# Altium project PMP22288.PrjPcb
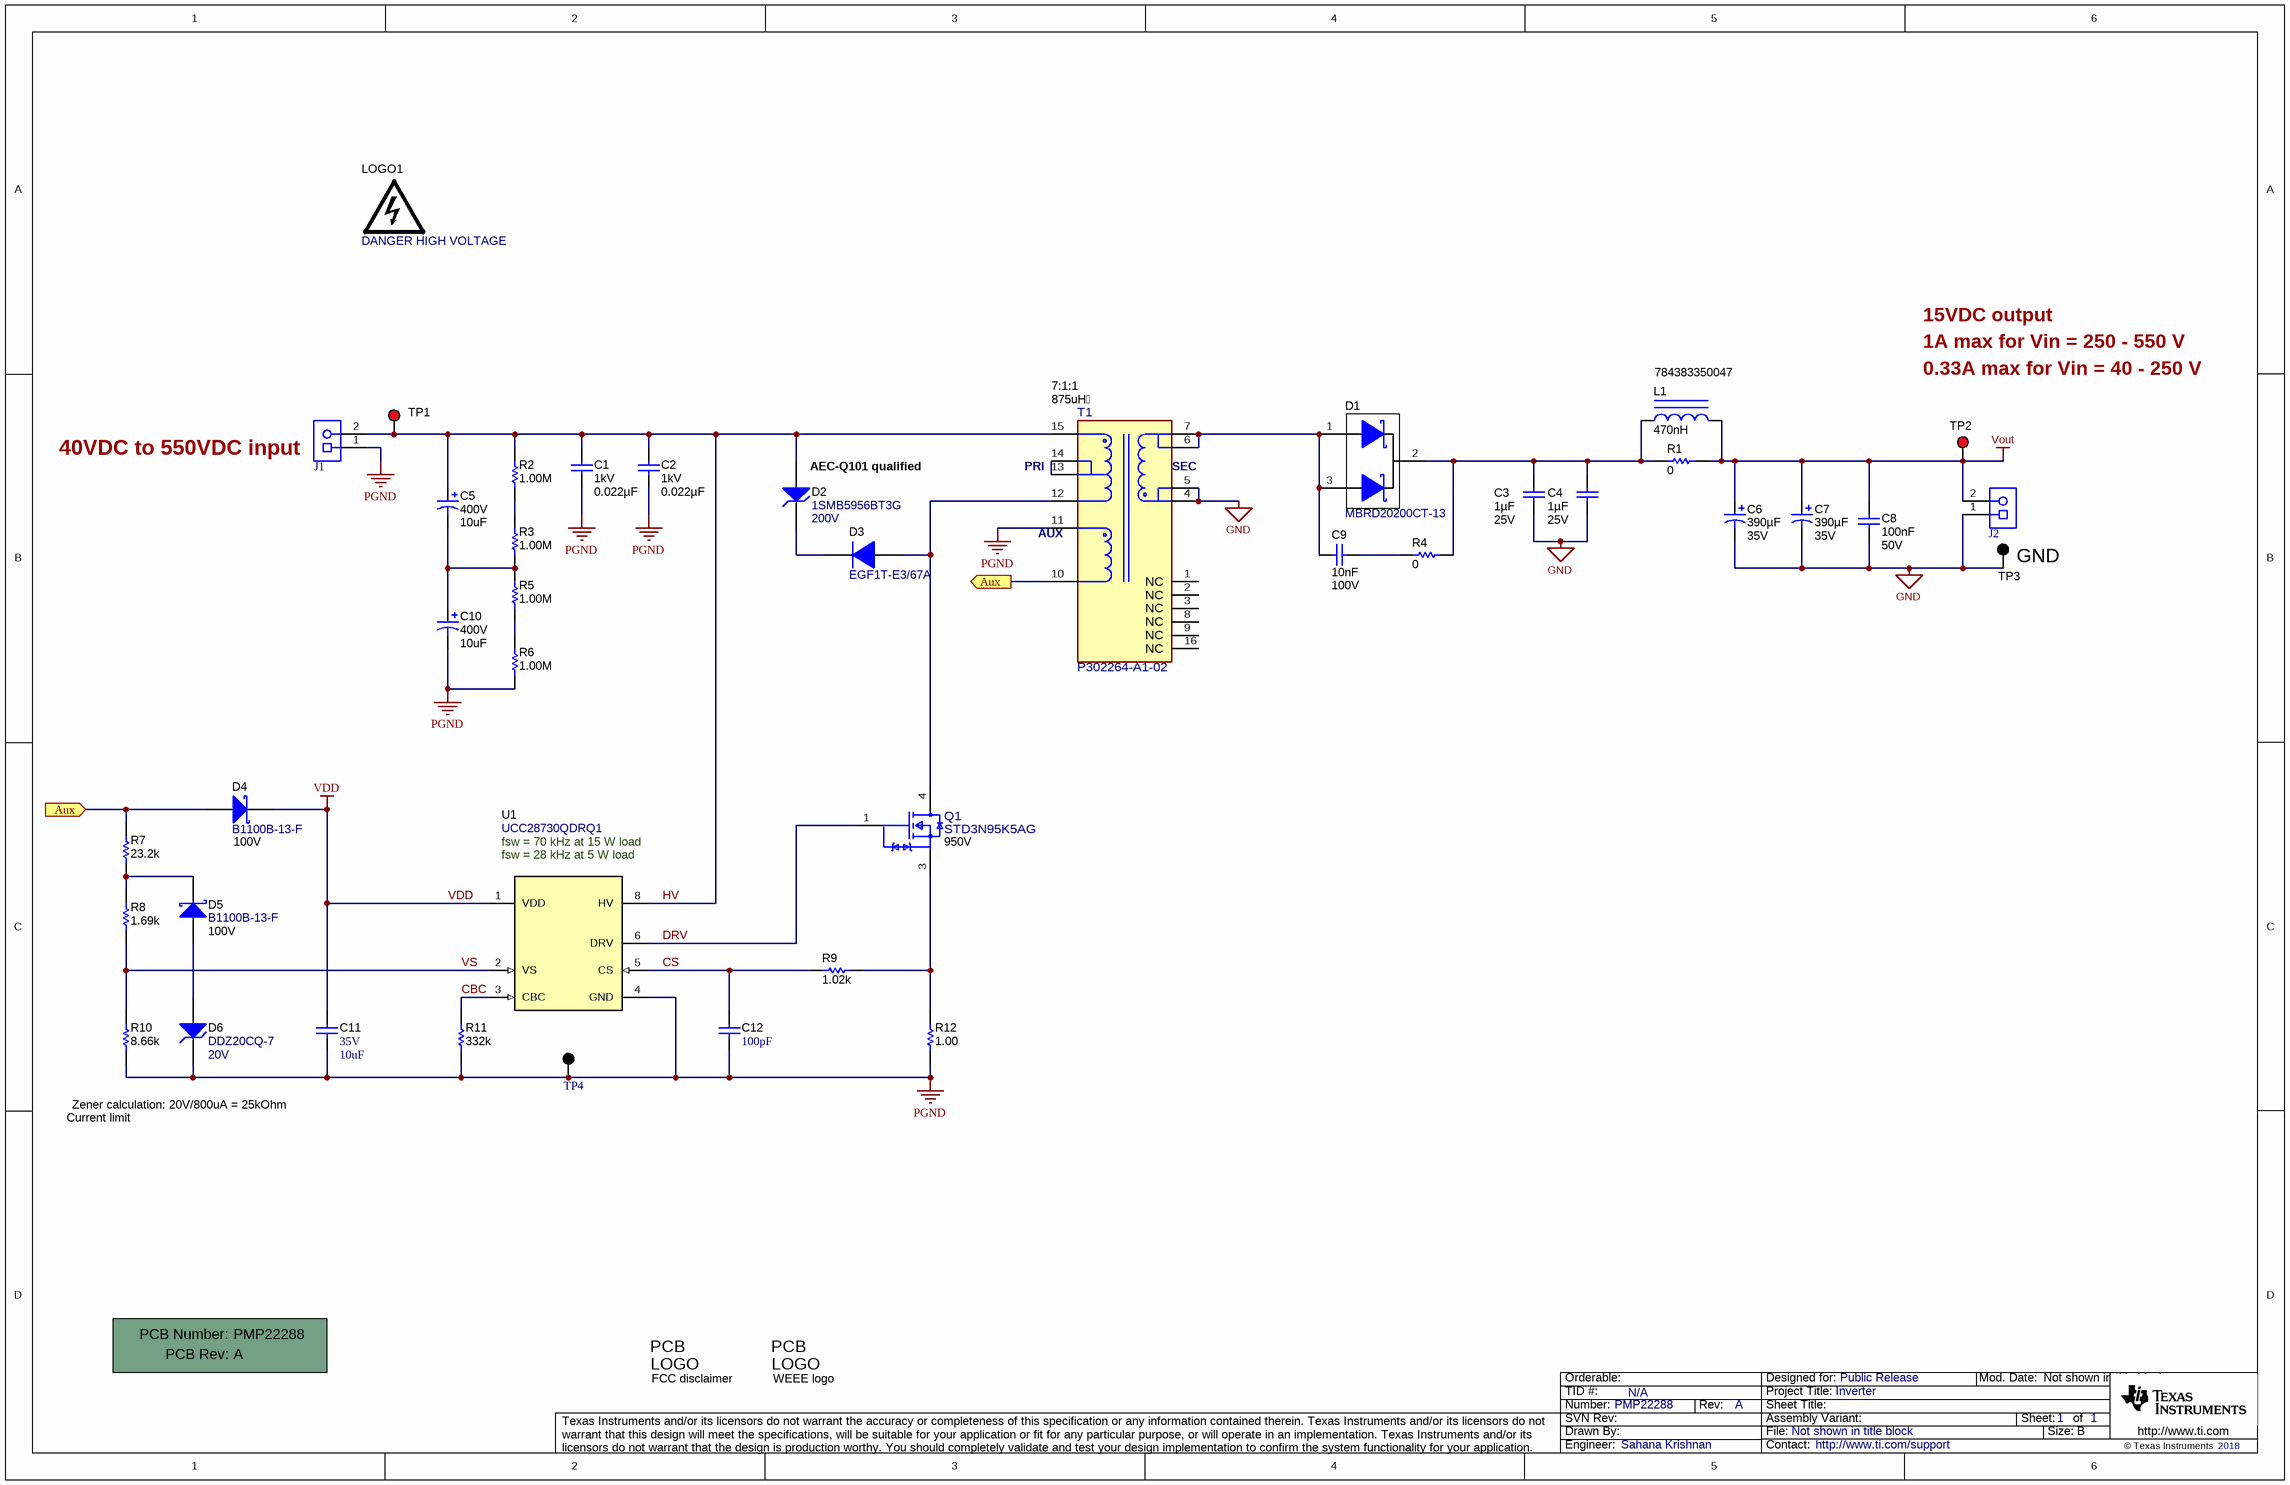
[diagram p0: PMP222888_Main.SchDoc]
CopyrightYear: 2018; PCB_Layout: Sahana Krishnan; PCB_Rev: A; PRJ_Customer: Public Release; PRJ_Engineer: Sahana Krishnan; PRJ_Number: PMP22288; PRJ_Title: Inverter; SCH_Rev: A; TechSupport: http://www.ti.com/support; TID: N/A
1 sheet, 44 parts. Net scope: flat (ports and power ports of the same name join across sheets).
Board file: PMP22288_PCB.PcbDoc

## Sheet PMP222888_Main.SchDoc
size 431 x 279 mm; Date: Not shown in title block; ApprovedBy: Not shown in title block; CheckedBy: Not shown in title block; Author: Not shown in title block; CompanyName: Not shown in title block; Engineer: Not shown in title block; Organization: Not shown in title block; Address1: Not shown in title block; Address2: Not shown in title block; Address3: Not shown in title block; Address4: Not shown in title block; DocumentNumber: 1; Revision: Use project parameter SCH_Rev; SheetNumber: 1; SheetTotal: 1; PageSetup: Record=PageOptions¦CenterHorizontal=True¦CenterVertical=True¦PrintScale=1.00¦XCorrection=1.00¦YCorrection=1.00¦PrintKind=0¦BorderSize=5000000¦LeftOffset=0¦BottomOffset=0¦Orientation=2¦PaperLength=1000¦PaperWidth=1000¦Scale=100¦PaperSource=15¦PrintQuality=600¦MediaType=1¦DitherType=10¦PaperKind=Letter¦PrintScaleMode=1

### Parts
!PCB1  Printed Circuit Board  (value not drawn)  (mechanical)
C1  VDC_V: 1kV  ValueDisplayed: 0.022µF  [1206_190]  (hidden comment: C1206C223KDRACTU)
C2  VDC_V: 1kV  ValueDisplayed: 0.022µF  [1206_190]  (hidden comment: C1206C223KDRACTU)
C3  Cap_F: 1µF  VDC_V: 25V  [0603]  (hidden comment: GRM188R71E105KA12D)
C4  Cap_F: 1µF  VDC_V: 25V  [0603]  (hidden comment: GRM188R71E105KA12D)
C5  VDC_V: 400V  ValueDisplayed: 10uF  [ULV_1000x1350]  (hidden comment: ULV2G100MNL1GS)
C6  ValueDisplayed: 390µF  VDC_V: 35V  [FC_1250x1500]  (hidden comment: EEU-FC1V391S)
C7  ValueDisplayed: 390µF  VDC_V: 35V  [FC_1250x1500]  (hidden comment: EEU-FC1V391S)
C8  Cap_F: 100nF  VDC_V: 50V  [0603]  (hidden comment: C0603C104K5RACAUTO)
C9  Cap_F: 10nF  VDC_V: 100V  [0603]  (hidden comment: CGA3E2X7R2A103K080AA)
C10  VDC_V: 400V  ValueDisplayed: 10uF  [ULV_1000x1350]  (hidden comment: ULV2G100MNL1GS)
C11  VDC_V: 35V  ValueDisplayed: 10uF  [1206_190]  (hidden comment: CGA5L1X7R1V106K160AC)
C12  ValueDisplayed: 100pF  [0603]  (hidden comment: CGA3E2NP01H101J080AA)
D1  MBRD20200CT-13  [DPAK]
D2  1SMB5956BT3G  value 200V  [SMB]
D3  EGF1T-E3/67A  [DO-214BA]
D4  B1100B-13-F  value 100V  [SMB]
D5  B1100B-13-F  value 100V  [SMB]
D6  DDZ20CQ-7  value 20V  [SOD-123]
J1  ED120/2DS  [On-Shore_ED120_2DS]  (value not drawn)
J2  ED120/2DS  [On-Shore_ED120_2DS]  (value not drawn)
L1  784383350047  ValueDisplayed: 470nH  [WE-MAIA_3015]
LOGO1  DANGER HIGH VOLTAGE  [IEC_HighVoltage_Small]  (no BOM)
Logo2  FCC disclaimer  [FCC_disclaimer]  (no BOM)
Logo3  WEEE logo  [WEEE_Minimum]  (no BOM)
Q1  STD3N95K5AG  VdsMax_V: 950V  [FP-STD3N95K5AG_DPAK-MFG]
R1  ValueDisplayed: 0  [1206]  (hidden comment: CRCW12060000Z0EA)
R2  ValueDisplayed: 1.00M  [1206]  (hidden comment: CRCW12061M00FKEA)
R3  ValueDisplayed: 1.00M  [1206]  (hidden comment: CRCW12061M00FKEA)
R4  ValueDisplayed: 0  [1206]  (hidden comment: CRCW12060000Z0EA)
R5  ValueDisplayed: 1.00M  [1206]  (hidden comment: CRCW12061M00FKEA)
R6  ValueDisplayed: 1.00M  [1206]  (hidden comment: CRCW12061M00FKEA)
R7  ValueDisplayed: 23.2k  [0603]  (hidden comment: CRCW060323K2FKEA)
R8  ValueDisplayed: 1.69k  [0603]  (hidden comment: CRCW06031K69FKEA)
R9  ValueDisplayed: 1.02k  [0603]  (hidden comment: CRCW06031K02FKEA)
R10  ValueDisplayed: 8.66k  [0603]  (hidden comment: CRCW06038K66FKEA)
R11  ValueDisplayed: 332k  [0402L]  (hidden comment: CRCW0402332KFKED)
R12  ValueDisplayed: 1.00  [1206]  (hidden comment: CSR1206FT1R00)
T1  P302264-A1-02  Ns1toNp: 7:1:1  Ind_H: 875uH  [FP-P302264-A1-51_SMD_TRANSFORMER_26MM0_22MM8-MFG]
TP1  5000  [Keystone5000]  (value not drawn)
TP2  5000  [Keystone5000]  (value not drawn)
TP3  5001  [Keystone5001]  (value not drawn)
TP4  5011  [Keystone5011]  (value not drawn)
U1  UCC28730QDRQ1  [D0007A_N]

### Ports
Aux (in), Aux (out)

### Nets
GND: C3.2 C4.2 C6.2(-) C7.2(-) C8.2 J2.1 T1.4 T1.5 TP3.1
PGND: C1.2 C2.2 C10.2(-) C11.2 C12.2 D6.1(K) J1.1 R6.2 R10.1 R11.1 R12.1 T1.11 TP4.1 U1.4(GND)
VDD: C11.1 D4.1(K) U1.1(VDD)
Vout: C6.1(+) C7.1(+) C8.1 J2.2 L1.2 R1.2 TP2.1
Aux: D4.2(A) R7.2 T1.10 ; port Aux
CBC: R11.2 U1.3(CBC)
CS: C12.1 R9.1 U1.5(CS)
DRV: Q1.1(G) U1.6(DRV)
HV: C1.1 C2.1 C5.1(+) D2.2(A) J1.2 R2.1 T1.15 TP1.1 U1.8(HV)
VS: R8.1 R10.2 U1.2(VS)
NetC3_1: C3.1 C4.1 D1.2(K) L1.1 R1.1 R4.2
NetC5_2: C5.2(-) C10.1(+) R3.2 R5.1
NetC9_1: C9.1 R4.1
NetC9_2: C9.2 D1.1(A) D1.3(A) T1.6 T1.7
NetD2_1: D2.1(K) D3.1(K)
NetD3_2: D3.2(A) Q1.4(D) T1.12
NetD5_1: D5.1(K) R7.1 R8.2
NetD5_2: D5.2(A) D6.2(A)
NetQ1_3: Q1.3(S) R9.2 R12.2
NetR2_2: R2.2 R3.1
NetR5_2: R5.2 R6.1
NetT1_13: T1.13 T1.14

Not connected (* = marked no-connect by the designer): T1 1(NC) 2(NC) 3(NC) 8(NC) 9(NC) 16(NC)

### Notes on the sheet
- 1A max for Vin = 250 - 550 V
- 15VDC output
- 0.33A max for Vin = 40 - 250 V
- (near J1) 40VDC to 550VDC input
- (near D2) AEC-Q101 qualified
- (near T1) PRI
- (near T1) SEC
- (near T1) AUX
- (near TP3) GND
- (near U1) fsw = 28 kHz at 5 W load
- fsw = 70 kHz at 15 W load
- Zener calculation: 20V/800uA = 25kOhm
- Current limit

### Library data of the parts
!PCB1 = CMP-0003618-2: Manufacturer: Any; PartNumber: PMP22288
C1 C2 = CMP-0084048-1: CAP, CERM, 0.022 µF, 1000 V,+/- 10%, X7R, AEC-Q200 Grade 1, 1206; Manufacturer: Kemet; TaMin_C: -55°C; Polarized: N; SizeAreaWB_mm2: 10.92; U/M: EA; Value: 0.022uF; TaMax_C: 125°C; SizeZ_mm: 1.9; SizeX_mm: 3.2; SizeY_mm: 1.6; Cap_Case: 1206; Value2: 1000V; SizeArea_mm2: 5.12; AEC Qualified: Y; Cap_F: 22nF; AEC Grade: 1; AEC Category: Q200
C3 C4 = CMP-0007405-4: CAP, CERM, 1 uF, 25 V, +/- 10%, X7R, 0603; Manufacturer: MuRata; TaMin_C: -55°C; Polarized: N; SizeAreaWB_mm2: 4.68; Value1: Unknown; U/M: EA; Value: 1uF; TaMax_C: 125°C; SizeZ_mm: 1; SizeX_mm: 1.6; SizeY_mm: 0.8; SizeArea_mm2: 1.28; AEC Category: Q200
C5 C10 = CMP-0011436-2: CAP, AL, 10 uF, 400 V, +/- 20%, SMD; Manufacturer: Nichicon; TaMin_C: -40°C; Polarized: Y; SizeAreaWB_mm2: 151.29; Value1: Unknown; U/M: EA; Value: 10uF; TaMax_C: 105°C; SizeZ_mm: 14.5; SizeX_mm: 10.3; Cap_Case: 10x13.5mm; SizeArea_mm2: 106.09; CompType: Capacitor; AEC Qualified: N; Cap_F: 10µF; IRMS_A: 55mA; AEC Category: Q200
C6 C7 = CMP-0860943-1: CAP, AL, 390 µF, 35 V, +/- 20%, AEC-Q200 Grade 2, TH; Manufacturer: Panasonic; SizeX_mm: 12.5; AEC Category: Q200; CompType: Capacitor; TaMax_C: 105°C; Polarized: Y; TaMin_C: -55°C; Cap_Case: 12.5x15mm; SizeArea_mm2: 156.25; Value: 390uF; IRMS_A: 1.205A; U/M: EA; SizeZ_mm: 16; AEC Grade: 2; SizeAreaWB_mm2: 210.25
C8 = CMP-0079602-1: CAP, CERM, 0.1 µF, 50 V,+/- 10%, X7R, AEC-Q200 Grade 1, 0603; Manufacturer: Kemet; TaMin_C: -55°C; Polarized: N; SizeAreaWB_mm2: 4.68; U/M: EA; Value: 0.1uF; TaMax_C: 125°C; SizeZ_mm: 1; SizeX_mm: 1.6; SizeY_mm: 0.8; SizeArea_mm2: 1.28; AEC Qualified: Y; AEC Category: Q200; ValueDisplayed: 0.1µF
C9 = CMP-0007082-1: CAP, CERM, 0.01 uF, 100 V, +/- 10%, X7R, AEC-Q200 Grade 1, 0603; Manufacturer: TDK; TaMin_C: -55°C; ESR_ohm: 0.235428; Polarized: N; SizeAreaWB_mm2: 4.68; Value1: 0.235428 ohm; U/M: EA; Value: 0.01uF; TaMax_C: 125°C; SizeZ_mm: 1; SizeX_mm: 1.6; SizeY_mm: 0.8; SizeArea_mm2: 1.28; AEC Qualified: Y; IRMS_A: 396.995mA; AEC Category: Q200
C11 = CMP-0008772-2: CAP, CERM, 10 uF, 35 V, +/- 10%, X7R, AEC-Q200 Grade 1, 1206_190; Manufacturer: TDK; TaMin_C: -55°C; ESR_ohm: 2.229m; Polarized: N; SizeAreaWB_mm2: 10.92; Value1: 0.002229 ohm; U/M: EA; Value: 10uF; TaMax_C: 125°C; SizeZ_mm: 1.9; SizeX_mm: 3.2; SizeY_mm: 1.6; SizeArea_mm2: 5.12; AEC Qualified: Y; Cap_F: 10µF; IRMS_A: 4.85932A; AEC Grade: 1; AEC Category: Q200
C12 = CMP-0007075-4: CAP, CERM, 100 pF, 50 V, +/- 5%, C0G/NP0, AEC-Q200 Grade 0, 0603; Manufacturer: TDK; TaMin_C: -55°C; Polarized: N; SizeAreaWB_mm2: 4.68; Value1: Unknown; U/M: EA; Value: 100pF; TaMax_C: 150°C; SizeZ_mm: 1; SizeX_mm: 1.6; SizeY_mm: 0.8; Value2: 50V; SizeArea_mm2: 1.28; AEC Qualified: Y; AEC Grade: 0; AEC Category: Q200
D1 = CMP-0081704-3: Diode, Schottky, 200 V, 10 A, AEC-Q101, DPAK; Manufacturer: Diodes Inc.; SizeZ_mm: 2.29; SizeX_mm: 9.91; Vr_V: 200V; AEC Qualified: Y; Vf_V: 900mV; Value2: 0.9V; SizeY_mm: 6.54; Value1: 10A; AEC Category: Q101; TJmax_C: 150°C; SizeAreaWB_mm2: 101.7114; Value: 200V; SizeArea_mm2: 64.8114
D2 = CMP-0005624-4: Diode, Zener, 200 V, 550 mW, SMB; Manufacturer: ON Semiconductor; RJA_CperW: 226; SizeArea_mm2: 21.336; Value1: 0.55W; SizeAreaWB_mm2: 44.156; SizeX_mm: 5.6; SizeZ_mm: 2.6; SizeY_mm: 3.81; Power_W: 550mW; AEC Category: Q101
D3 = CMP-0077733-2: Diode, Ultrafast, 1300 V, 1 A, AEC-Q101, DO-214BA; Manufacturer: Vishay-Semiconductor; Value: 1300V; SizeAreaWB_mm2: 41.588; SizeArea_mm2: 19.548; Io_A: 1A; SizeX_mm: 5.4; AEC Category: Q101; RJC_CperW: 20.0; SizeZ_mm: 3.3; Vr_V: 1.3kV; Vf_V: 3V; SizeY_mm: 3.62; TJmax_C: 150°C; AEC Qualified: Y
D4 D5 = CMP-0028372-1: Diode, Schottky, 100 V, 1 A, SMB; Manufacturer: Diodes Inc.; Io_A: 1A; Green_Lifecycle: Not Set; SizeAreaWB_mm2: 44.156; Green_REACh: Incomplete; TJmax_C: 150°C; U/M: EA; SizeZ_mm: 2.6; SizeX_mm: 5.6; SizeY_mm: 3.81; Vf_V: 790mV; Value2: 0.79V; SizeArea_mm2: 21.336; AEC Category: Q101; RJC_CperW: 25
D6 = CMP-0085147-1: Diode, Zener, 20 V, 500 mW, AEC-Q101, SOD-123; Manufacturer: Diodes Inc.; SizeX_mm: 3.85; AEC Category: Q101; SizeAreaWB_mm2: 13.095; SizeArea_mm2: 6.545; RJA_CperW: 425; SizeY_mm: 1.7; AEC Qualified: Y; SizeZ_mm: 1.35; Value1: 0.5W; Power_W: 500mW
J1 J2 = CMP-0074910-1: Terminal Block, 5.08 mm, 2x1, Brass, TH; Manufacturer: On-Shore Technology; Cert_VDE: Y; CNHeader: False; Current_A: 15A; Green_Lifecycle: Not Set; Shrouded: N; Gender: Female; Green_REACh: Incomplete; Voltage_V: 300V; Row_Count: 1; Pitch_mm: 5.08; CT: True
L1 = CMP-0064355-1: Inductor, Shielded, Powdered Iron, 470 nH, 4.6 A, 0.023 ohm, AEC-Q200 Grade 1, SMD; Manufacturer: Wurth Elektronik; Isat: 5.8A @ 20% inductance drop; Irms: 4.6A @ 40C rise; SizeAreaWB_mm2: 16; DCR_ohm: 0.023; Value: 470nH; Imax_A: 4.6A; SizeZ_mm: 1.5; SizeX_mm: 3; SizeArea_mm2: 9; AEC Qualified: Y; AEC Grade: 1; AEC Category: Q200
LOGO1 = CMP-0074835-1: IEC 61010-1 High Voltage Warning; SymbolCreator: a0412235
Logo2 = CMP-0074847-1: FCC_disclaimer; Library Reference: Logo
Logo3 = CMP-0074769-1
Q1 = CMP-0088095-1: N-Channel 950V 2A (Tc) 45W (Tc) Surface Mount DPAK; Manufacturer: STMicroelectronics; SizeZ_mm: 2.63mm; QgTyp_nC: 3.4nC @ 10V; AEC Qualified: Yes; ChMode: False; Rdson45_ohm: 4.3; Vgs_V: 30V
R1 R4 = CMP-0018573-3: RES, 0, 5%, 0.25 W, AEC-Q200 Grade 0, 1206; Manufacturer: Vishay-Dale; Power_W: 250mW; TempCo: 200 ppm/C; Value_Code: 0000; Value: 0; EIA_Code: E24; SizeX_mm: 3.2; SizeY_mm: 1.6; SizeZ_mm: 1.35; Value2: 0.25W; SizeArea_mm2: 5.12; AEC Qualified: Y; VDC_V: 200V; AEC Category: Q200
R2 R3 R5 R6 = CMP-0016716-3: RES, 1.00 M, 1%, 0.25 W, AEC-Q200 Grade 0, 1206; Manufacturer: Vishay-Dale; Power_W: 250mW; TempCo: 100 ppm/C; Value_Code: 1M00; Value: 1.00Meg; EIA_Code: E96; Res_ohm: 1M; SizeX_mm: 3.2; SizeY_mm: 1.6; SizeZ_mm: 1.35; Value2: 0.25W; SizeArea_mm2: 5.12; AEC Qualified: Y; VDC_V: 200V; AEC Category: Q200; AEC Grade: 0
R7 = CMP-0022228-4: RES, 23.2 k, 1%, 0.1 W, AEC-Q200 Grade 0, 0603; Manufacturer: Vishay-Dale; Power_W: 100mW; TempCo: 100 ppm/C; Value_Code: 23k2; Value: 23.2k; EIA_Code: E96; SizeX_mm: 1.6; SizeY_mm: 0.8; SizeZ_mm: 1; Value2: 0.1W; SizeArea_mm2: 1.28; AEC Qualified: Y; VDC_V: 75V; AEC Category: Q200; AEC Grade: 0
R8 = CMP-0022131-4: RES, 1.69 k, 1%, 0.1 W, AEC-Q200 Grade 0, 0603; Manufacturer: Vishay-Dale; Power_W: 100mW; TempCo: 100 ppm/C; Value_Code: 1k69; Value: 1.69k; EIA_Code: E96; SizeX_mm: 1.6; SizeY_mm: 0.8; SizeZ_mm: 1; Value2: 0.1W; SizeArea_mm2: 1.28; AEC Qualified: Y; VDC_V: 75V; AEC Category: Q200; AEC Grade: 0
R9 = CMP-0022110-4: RES, 1.02 k, 1%, 0.1 W, AEC-Q200 Grade 0, 0603; Manufacturer: Vishay-Dale; Power_W: 100mW; TempCo: 100 ppm/C; Value_Code: 1k02; Value: 1.02k; EIA_Code: E96; SizeX_mm: 1.6; SizeY_mm: 0.8; SizeZ_mm: 1; Value2: 0.1W; SizeArea_mm2: 1.28; AEC Qualified: Y; VDC_V: 75V; AEC Category: Q200; AEC Grade: 0
R10 = CMP-0022637-4: RES, 8.66 k, 1%, 0.1 W, AEC-Q200 Grade 0, 0603; Manufacturer: Vishay-Dale; Power_W: 100mW; TempCo: 100 ppm/C; Value_Code: 8k66; Value: 8.66k; EIA_Code: E96; SizeX_mm: 1.6; SizeY_mm: 0.8; SizeZ_mm: 1; Value2: 0.1W; SizeArea_mm2: 1.28; AEC Qualified: Y; VDC_V: 75V; AEC Category: Q200; AEC Grade: 0
R11 = CMP-0026296-2: RES, 332 k, 1%, 0.063 W, AEC-Q200 Grade 0, 0402; Manufacturer: Vishay-Dale; Power_W: 63mW; TempCo: 100 ppm/C; Value: 332k; EIA_Code: E96; SizeX_mm: 1; SizeY_mm: 0.5; SizeZ_mm: 0.6; Value2: 0.063W; AEC Qualified: Y; VDC_V: 50V; AEC Category: Q200; AEC Grade: 0
R12 = CMP-0017272-2: RES, 1.00, 1%, 0.5 W, 1206; Manufacturer: Stackpole Electronics Inc; Power_W: 500mW; TempCo: 100 ppm/C; Value_Code: 1R00; U/M: EA; Value: 1.00; EIA_Code: E96; Res_ohm: 1; SizeX_mm: 3.2; SizeY_mm: 1.6; SizeZ_mm: 1.35; Value2: 0.5W; SizeArea_mm2: 5.12; AEC Category: Q200
T1 = CMP-0088107-1: Flyback Transformer; PartNumber: P302264-A1-54; Manufacturer: TDK; Rsec1_ohm: 0.13; Symbol Name: SYM-P302264-A1-54; DCR_ohm: 3.2; SizeZ_mm: 17.3mm; AEC Grade: Grade 0; AEC Qualified: Yes
TP1 TP2 = CMP-0055137-1: Test Point, Miniature, Red, TH; Manufacturer: Keystone; ContactFinish: Silver; Green_Lifecycle: Active; Green_REACh: Passed; CNHeader: FALSE; CT: TRUE
TP3 = CMP-0055138-1: Test Point, Miniature, Black, TH; Manufacturer: Keystone; ContactFinish: Silver; Green_Lifecycle: Active; Green_REACh: Passed; CNHeader: FALSE; CT: TRUE
TP4 = CMP-0055148-1: Test Point, Multipurpose, Black, TH; Manufacturer: Keystone; CNHeader: FALSE; Green_Lifecycle: Active; Green_REACh: Passed; ContactFinish: Silver; CT: TRUE
U1 = CMP-0065056-3: Zero Standby PSR Flyback Controller with CVCC and Wake-Up Monitoring, Automotive, D0007A (SOIC-7); Manufacturer: Texas Instruments; SizeX_mm: 6.0; SizeY_mm: 4.9; CompType: IC; SizeZ_mm: 1.75; SizeArea_mm2: 29.4; SizeAreaWB_mm2: 55.2; U/M: EA; AEC Category: Q200; AEC Qualified: N

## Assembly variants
001: not fitted C9 L1 R4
